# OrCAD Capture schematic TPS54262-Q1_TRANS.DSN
size D; title: TPS54262-Q1 Automotive 2-A 60-V Step-Down DC-DC; rev: 1.0; note: Datasheet: SLVS996D        EVM: SLVU344
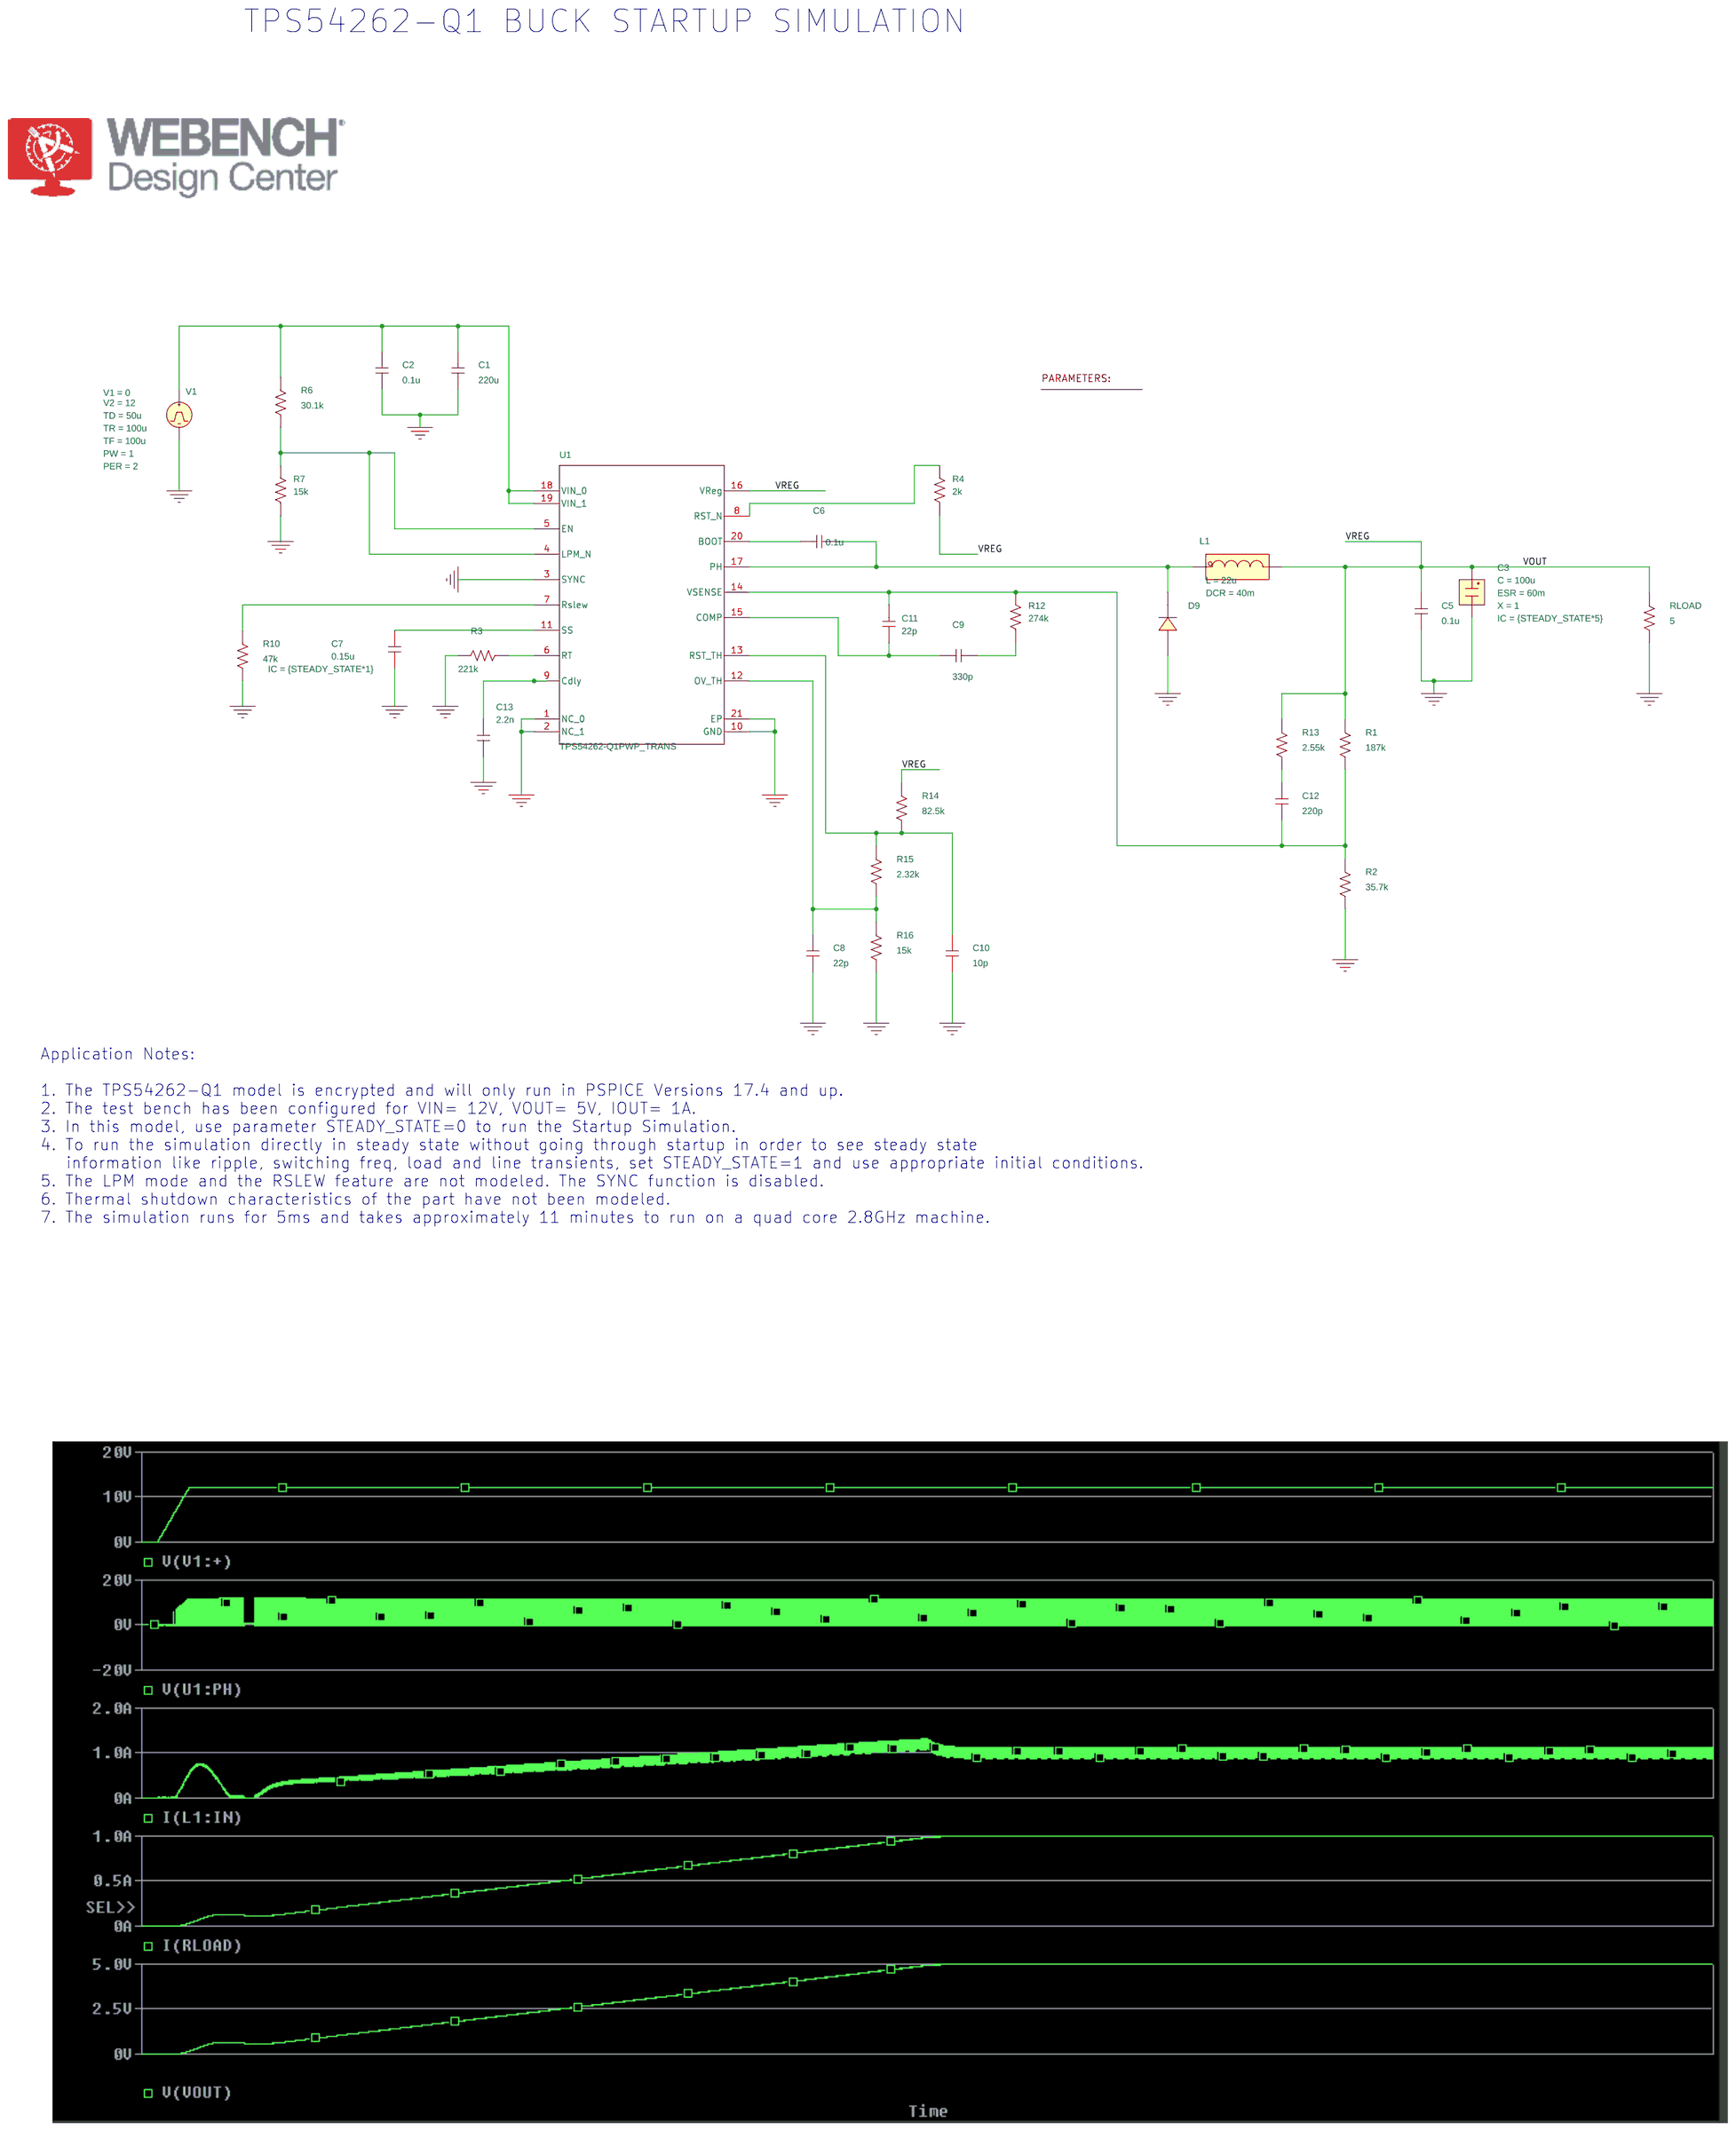
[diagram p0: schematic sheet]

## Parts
1  PARAM
C1  220u  [RAD/CK05]
C2  0.1u  [RAD/CK05]
C3  CESR
C5  0.1u  [RAD/CK05]
C6  0.1u  [RAD/CK05]
C7  0.15u  [RAD/CK05]
C8  22p  [RAD/CK05]
C9  330p  [RAD/CK05]
C10  10p  [RAD/CK05]
C11  22p  [RAD/CK05]
C12  220p  [RAD/CK05]
C13  2.2n  [RAD/CK05]
D9  D_D1
L1  LDCR
R1  187k  [AX/RC05]
R2  35.7k  [AX/RC05]
R3  221k  [AX/RC05]
R4  2k  [AX/RC05]
R6  30.1k  [AX/RC05]
R7  15k  [AX/RC05]
R10  47k  [AX/RC05]
R12  274k  [AX/RC05]
R13  2.55k  [AX/RC05]
R14  82.5k  [AX/RC05]
R15  2.32k  [AX/RC05]
R16  15k  [AX/RC05]
RLOAD  5  [AX/RC05]
U1  TPS54262-Q1PWP_TRANS  [PWP0020M-IPC_A]
V1  VPULSE

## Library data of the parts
1 = PARAM: STEADY_STATE: 0
C1 C2 C5 C6 C8-C13 = C
C3 = CESR: C: 100u; ESR: 60m; IC: {STEADY_STATE*5}; PSpiceTemplate: X^@REFDES %IN %OUT @MODEL PARAMS:  ?C|C=@C||C=100u|  ?ESR|ESR=@ESR||ESR=0.01| ?X|X=@X||X=2|  ?IC|IC=@IC||IC=2|; X: 1
C7 = C: IC: {STEADY_STATE*1}
D9 = D_D1
L1 = LDCR: DCR: 40m; IC: 0; L: 22u; PSpiceTemplate: X^@REFDES %IN %OUT @MODEL PARAMS:  ?L|L=@L||L=1u|  ?DCR|DCR=@DCR||DCR=0.01| ?IC|IC=@IC||IC=0|
R1-R4 R6 R7 R10 R12-R16 RLOAD = R
U1 = TPS54262-Q1PWP_TRANS
V1 = VPULSE: PER: 2; PW: 1; TD: 50u; TF: 100u; TR: 100u; V1: 0; V2: 12

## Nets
0: C1.2 C2.2 C3.3(OUT) C5.2 C7.2 C8.2 C10.2 C13.2 D9.2(A) R2.2 R3.2 R7.1 R10.2 R16.2 RLOAD.2 U1.1(NC_0) U1.2(NC_1) U1.3(SYNC) U1.10(GND) U1.21(EP) V1.2(-)
VOUT: C3.1(IN) C5.1 L1.3(OUT) R1.1 R4.1 R13.1 R14.1 RLOAD.1 U1.16(VReg)
N16764540: C1.1 C2.1 R6.1 U1.18(VIN_0) U1.19(VIN_1) V1.1(+)
N16764694: R6.2 R7.2 U1.4(LPM_N) U1.5(EN)
N16764784: R4.2 U1.8(RST_N)
N16764902: C6.2 U1.20(BOOT)
N16764906: C6.1 D9.1(C) L1.1(IN) U1.17(PH)
N16765054: C11.2 C12.2 R1.2 R2.1 R12.2 U1.14(VSENSE)
N16765074: R10.1 U1.7(Rslew)
N16765158: C9.2 C11.1 U1.15(COMP)
N16765186: C7.1 U1.11(SS)
N16765272: C9.1 R12.1
N16765288: R3.1 U1.6(RT)
N16765292: C10.1 R14.2 R15.1 U1.13(RST_TH)
N16765324: C13.1 U1.9(Cdly)
N16765336: C8.1 R15.2 R16.1 U1.12(OV_TH)
N16765518: C12.1 R13.2

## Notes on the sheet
- TPS54262-Q1 BUCK STARTUP SIMULATION
- Application Notes:
  1. The TPS54262-Q1 model is encrypted and will only run in PSPICE Versions 17.4 and up.
  2. The test bench has been configured for VIN= 12V, VOUT= 5V, IOUT= 1A.
  3. In this model, use parameter STEADY_STATE=0 to run the Startup Simulation.
  4. To run the simulation directly in steady state without going through startup in order to see steady state
     information like ripple, switching freq, load and line transients, set STEADY_STATE=1 and use appropriate initial conditions.
  5. The LPM mode and the RSLEW feature are not modeled. The SYNC function is disabled.
  6. Thermal shutdown characteristics of the part have not been modeled.
  7. The simulation runs for 5ms and takes approximately 11 minutes to run on a quad core 2.8GHz machine.
